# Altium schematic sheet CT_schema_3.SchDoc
size 316 x 185 mm
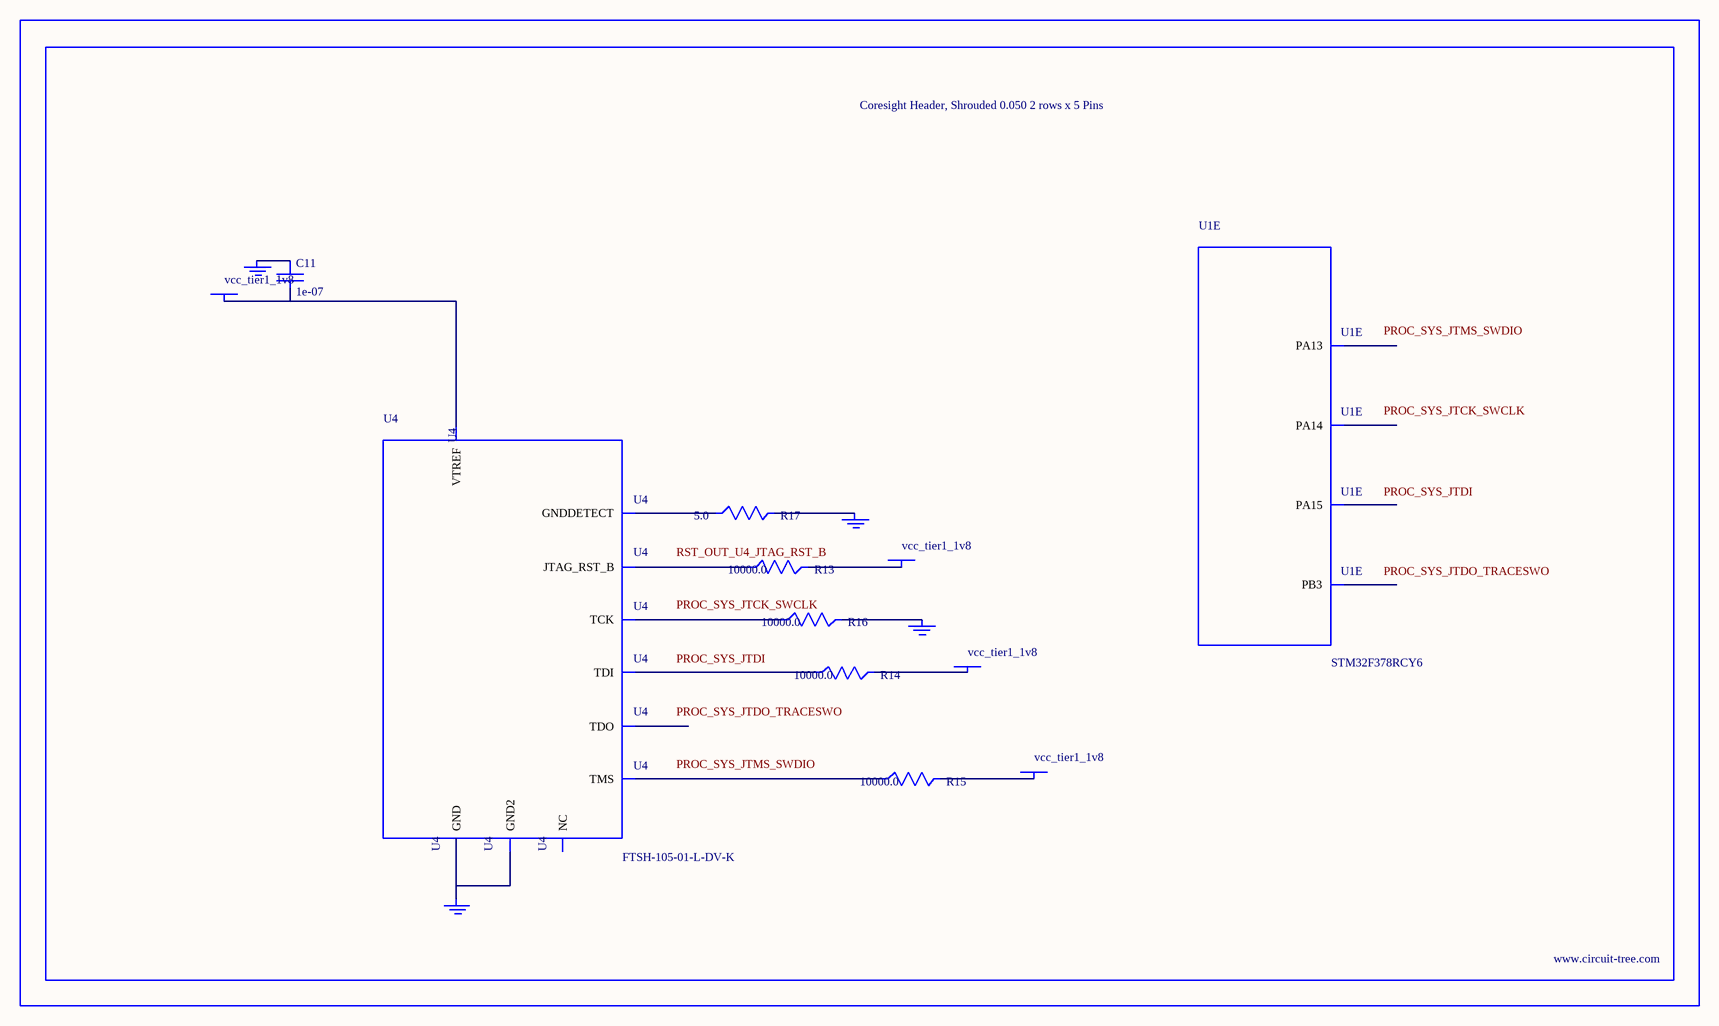
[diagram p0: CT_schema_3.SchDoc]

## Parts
BORDER2  (no value)
C11  1e-07  [C0402]
GND_INSTANCE_2_0  (no value)
GND_INSTANCE_2_1  (no value)
GND_INSTANCE_2_2  (no value)
GND_INSTANCE_2_3  (no value)
POWER_INSTANCE_2_0  vcc_tier1_1v8
POWER_INSTANCE_2_1  vcc_tier1_1v8
POWER_INSTANCE_2_2  vcc_tier1_1v8
POWER_INSTANCE_2_3  vcc_tier1_1v8
R13  10000.0  [R0603]
R14  10000.0  [R0603]
R15  10000.0  [R0603]
R16  10000.0  [R0603]
R17  5.0  [R0603]
U1  STM32F378RCY6  [WLCSP66_8X8]  (part E of 6)
U4  FTSH-105-01-L-DV-K  [SAMTEC_FTSH-105-01-L-DV-K]

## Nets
NetC11_1: C11.1 GND_INSTANCE_2_0.0(GND)
NetC11_2: C11.2 POWER_INSTANCE_2_0.0(PWR) U4.1(VTREF)
NetGND_INSTANCE_2_1_0: GND_INSTANCE_2_1.0(GND) R16.2
NetGND_INSTANCE_2_2_0: GND_INSTANCE_2_2.0(GND) R17.2
NetGND_INSTANCE_2_3_0: GND_INSTANCE_2_3.0(GND) U4.3(GND) U4.5(GND2)
NetPOWER_INSTANCE_2_1_0: POWER_INSTANCE_2_1.0(PWR) R15.2
NetPOWER_INSTANCE_2_2_0: POWER_INSTANCE_2_2.0(PWR) R14.2
NetPOWER_INSTANCE_2_3_0: POWER_INSTANCE_2_3.0(PWR) R13.2
NetR13_1: R13.1 U4.10(JTAG_RST_B)
NetR14_1: R14.1 U4.8(TDI)
NetR15_1: R15.1 U4.2(TMS)
NetR16_1: R16.1 U4.4(TCK)
NetR17_1: R17.1 U4.9(GNDDETECT)

Not connected (* = marked no-connect by the designer): U1 A1(PA14) A2(PA15) C4(PA13) C5(PB3); U4 6(TDO) 7(NC)

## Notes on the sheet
- Labels drawn without touching a wire or pin: PROC_SYS_JTCK_SWCLK, PROC_SYS_JTDI, PROC_SYS_JTDO_TRACESWO, PROC_SYS_JTMS_SWDIO, RST_OUT_U4_JTAG_RST_B

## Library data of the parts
BORDER2 = BORDER_PAGE2
C11 = C0402C104K3RACTU
GND_INSTANCE_2_0-GND_INSTANCE_2_3 = GND
POWER_INSTANCE_2_0-POWER_INSTANCE_2_3 = PWR
R13-R16 = RC0603JR-0710KL
R17 = ERJ-3GEYJ5R1V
